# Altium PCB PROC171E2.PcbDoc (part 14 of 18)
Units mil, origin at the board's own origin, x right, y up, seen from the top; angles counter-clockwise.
Board outline 7700 x 2300 mil, 6 copper layers (Top Layer, GND 1, SIG 1, SIG 2, GND 2, Bottom Layer), stack 61.062 mil thick; 937 components, 687 nets, 11931 pads, 1719 vias.
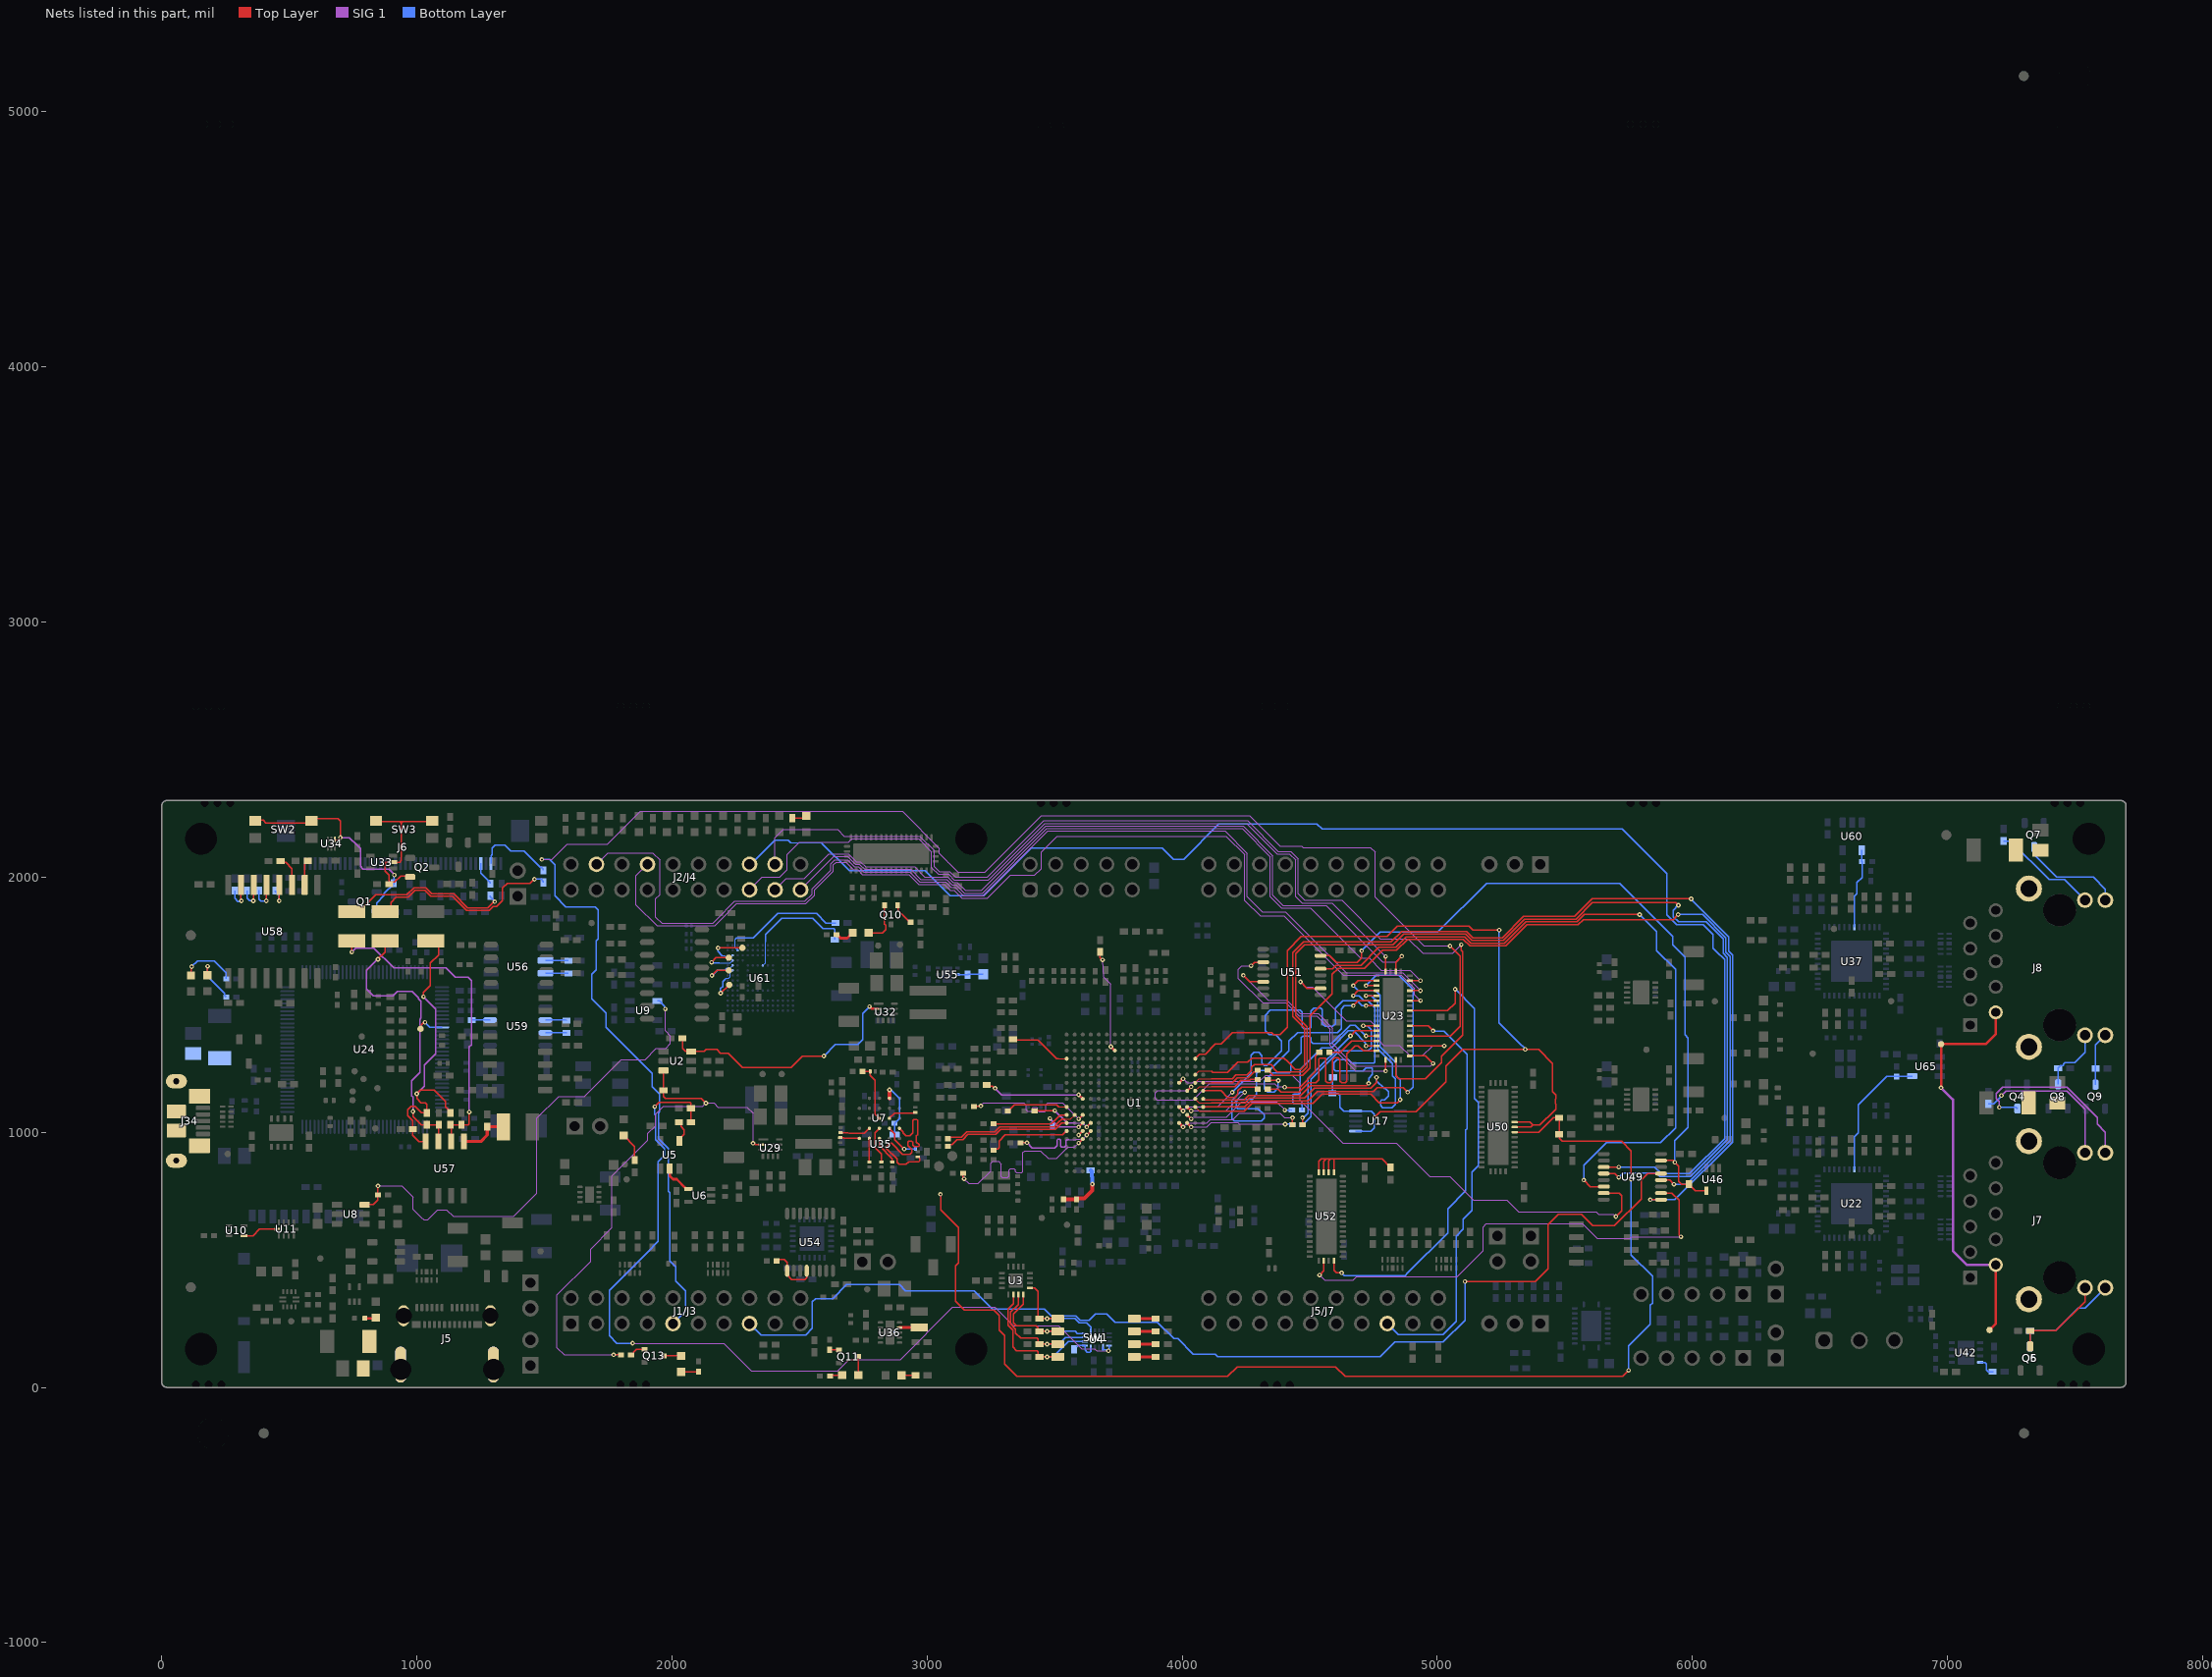
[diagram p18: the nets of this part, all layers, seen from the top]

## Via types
v1: diameter 18, hole 8, Top Layer to Bottom Layer, tented both sides, 1588 vias
v2: diameter 19.68, hole 7.87, Top Layer to Bottom Layer, tented both sides, 104 vias
v3: diameter 19.68, hole 7.87, Top Layer to Bottom Layer, 24 vias
v4: diameter 18, hole 8, Top Layer to Bottom Layer, 3 vias

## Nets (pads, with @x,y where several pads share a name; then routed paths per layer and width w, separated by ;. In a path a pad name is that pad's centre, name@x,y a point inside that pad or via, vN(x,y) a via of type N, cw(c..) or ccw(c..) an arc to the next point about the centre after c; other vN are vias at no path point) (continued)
NetC257_1: C257.1 R189.1 R190.1 U1.N3 | length 233.8
  Top Layer w5.3: v1(3594.38,989.09) U1.N3@3610.13,1004.84
  Top Layer w15: R190.1@3535,736.82 R189.1@3586.2,736.82 3586.2,738.78 3588.54,741.13 3617.5,741.13 3648.19,771.82 v1(3648.19,796.75)
  Bottom Layer w15: C257.1@3640.73,851 3641.45,851 3645.76,846.69 3645.76,826.66 3648.19,824.23 3648.19,815.87 v1(3648.19,796.75)
NetC266_1: C266.1 U61.C2 | length 497.7
  Bottom Layer w3.4: 2249.26,1757.01 2247.89,1755.65 2247.89,1722.93 U61.C2@2257.75,1713.07
  Bottom Layer w5.3: 2249.14,1757.13 2253.98,1761.97 2319.33,1761.97 2414.7,1857.34 2567.23,1857.34 2604.32,1820.24 C266.1@2641.33,1820.24
NetD2_2: D2.2 R257.1 | length 114.5
  Top Layer w5.3: D2.2@1810.94,987.31 1853.71,944.54 R257.1@1853.71,890.52
NetD3_2: D3.2 R259.1 | length 186.5
  Top Layer w5.3: D3.2@178.78,1615.52 179.85,1616.59 v1(179.85,1650.66)
  Bottom Layer w5.3: v1(179.85,1650.66) 179.85,1612.12 247.28,1544.69 247.28,1535.63 R259.1@252.92,1530
NetD4_2: D4.2 R313.1 | length 58.7
  Top Layer w5.3: R313.1@2471.37,2231 2517.62,2231 D4.2@2526.43,2239.8
NetD5_1: D5.1 Q13.3 | length 68.9
  Top Layer w5.3: Q13.3@1967.4,123.39 D5.1@2036.27,123.39
NetD5_2: D5.2 R314.1 | length 68
  Top Layer w5.3: D5.2@2036.27,60.4 2101.71,60.4 R314.1@2103.52,62.21
NetD6_2: D6.2 R315.1 | length 55
  Top Layer w5.3: D6.2@2899.99,47.06 2900.24,47.31 R315.1@2954.87,47.31
NetDS1_1: DS1.1 Q10.2 | length 169.1
  Top Layer w5.3: DS1.1@2770.91,1781.37 2824.91,1781.37 2837.72,1794.18 2837.72,1810.86 2833.47,1815.12 Q10.2@2833.47,1889.43
NetDS1_2: DS1.2 R265.1 | length 76.4
  Top Layer w12: R265.1@2645.6,1774.32 2647.57,1774.32 2661.07,1760.82 2687.37,1760.82 DS1.2@2707.92,1781.37
NetDS2_1: DS2.1 Q11.3 | length 73.1
  Top Layer w5.3: Q11.3@2729.93,120.9 2729.93,48.41 DS2.1@2730.37,47.97
NetDS2_2: DS2.2 R302.1 | length 49.3
  Top Layer w5.3: R302.1@2619.3,45 2622.27,47.97 DS2.2@2667.38,47.97
NetDS3_2: DS3.2 R260.1 | length 224.4
  Top Layer w5.3: DS3.2@115.08,1614.97 115.08,1646.45 v1@118.65,1650.03
  Bottom Layer w5.3: v1(117.38,1649.19) 139.6,1671.41 206.46,1671.41 252.92,1624.95 R260.1@252.92,1601.11
NetDS4_2: DS4.2 R434.1 | length 43.2
  Top Layer w10: R434.1@796.23,270.76 836.78,270.76 DS4.2@838.68,272.66
NetJ6_36: J6.36 R355.2 | length 94.1
  Bottom Layer w5.3: J6.36@1250.75,2053.35 1250.75,2015.97 1288.1,1978.61 R355.2@1288.1,1974.68
NetJ6_38: J6.38 R357.2 | length 311.3
  Bottom Layer w5.3: J6.38@1290.12,2053.35 1291.04,2054.27 1291.04,2083.42 1295.52,2087.91 1295.52,2114.52 1306,2125 1344.61,2125 1368.1,2101.52 1421.11,2101.52 1482.9,2039.72 1486.84,2039.72 1496,2030.56 R357.2@1496,2026.62
NetL4_1: L4.1 U36.9 | length 58.3
  Top Layer w10: U36.9@2892.11,234.65 2943.72,234.65 L4.1@2948.45,239.38
NetQ10_1: Q10.1 R272.2 | length 88.2
  Top Layer w5.3: Q10.1@2884.65,1889.43 2887.02,1887.06 2887.02,1869.67 2933.35,1823.35 R272.2@2935.31,1823.35
NetQ11_1: Q11.1 R303.2 | length 37.9
  Top Layer w5.3: R303.2@2617.63,147.36 2618.5,146.49 Q11.1@2655.13,146.49
NetQ13_1: Q13.1 R317.2 | length 63
  Top Layer w5.3: R317.2@1839.67,127.49 1841.64,127.49 1848.84,134.68 1848.84,136.65 1861.17,148.98 Q13.1@1892.6,148.98
NetR8_2: R8.2 U4.4 U4.5 | length 96.2
  Bottom Layer w5.3: R8.2@3586.45,158.78 3591.82,164.16 U4.5@3618.83,164.16 3618.83,146.31 3627.93,137.2 3637.86,137.2 3642.45,141.79 U4.4@3642.45,156.28
NetR22_2: R22.2 SW1.1 | length 84.4
  Top Layer w12: SW1.1@3812.01,119.51 R22.2@3896.38,119.51
NetR23_2: R23.2 SW1.2 | length 84.4
  Top Layer w12: SW1.2@3812.01,169.51 R23.2@3896.38,169.51
NetR24_2: R24.2 SW1.3 | length 84.4
  Top Layer w12: SW1.3@3812.01,219.51 R24.2@3896.38,219.51
NetR25_2: R25.2 SW1.4 | length 84.4
  Top Layer w12: SW1.4@3812.01,269.51 R25.2@3896.38,269.51
NetR165_2: R165.2 U1.M3 | length 178.3
  Top Layer w5.3: v1(3594.38,1020.59) U1.M3@3610.13,1036.34
  SIG 1 w5.3: v1(3481.61,1054.11) 3515.13,1020.59 v1(3594.38,1020.59)
  Bottom Layer w5.3: v1(3481.61,1054.11) 3481.61,1053.87 3490.83,1044.65 3490.83,1030.45 R165.2@3492.19,1029.09
NetR167_2: R167.2 U1.L1 | length 302.3
  Top Layer w5.3: R167.2@3260.59,1034.08 3262.76,1031.91 3487.02,1031.91 3515.64,1060.52 3522.95,1067.84 U1.L1@3547.13,1067.84
NetR168_2: R168.2 U1.K1 | length 242.4
  Top Layer w4: 3515.64,1099.42 3547.05,1099.42 U1.K1@3547.13,1099.33
  Top Layer w5.3: R168.2@3317.18,1083.59 3319.15,1083.59 3342.09,1106.53 3508.44,1106.53 3515.55,1099.42 3515.64,1099.42
NetR249_2: R249.2 U42.4 | length 81.8
  Bottom Layer w5.3: U42.4@7127.91,98.07 7147.67,98.07 7153.38,92.36 7153.38,68.08 7160,61.46 R249.2@7180.31,61.46
NetR256_2: R256.2 U52.18 U52.19 U52.20 U52.21 | length 504.7
  Top Layer w5.3: U52.21@4535.47,843.23 4535.47,885.47 4545.28,895.28 4565,895.28 ; U52.20@4555.16,843.23 4555.16,885.44 4565,895.28 ; U52.19@4574.84,843.23 4574.84,888.3 4581.82,895.28 ; U52.18@4594.53,843.23 4594.53,895.28 ; R256.2@4816.77,861.65 4783.14,895.28 4594.53,895.28 ; 4565,895.28 4581.82,895.28 ; 4581.82,895.28 4594.53,895.28
NetR342_1: R342.1 U58.15 | length 121
  Top Layer w5.3: U58.15@310.25,1969.74 310.2,1969.79 310.2,1908.8 v1(312,1907)
  Bottom Layer w5.3: R342.1@287,1947.38 287,1917 299,1905 v1@309,1905
NetR343_1: R343.1 U58.14 | length 119.6
  Top Layer w5.3: v1@358,1910 360.25,1912.25 U58.14@360.25,1969.74
  Bottom Layer w5.3: R343.1@334.13,1947.37 334.13,1917.87 345,1907 v1(359,1907)
NetR344_1: R344.1 U58.13 | length 125.7
  Top Layer w5.3: v1(410,1907) 410.25,1907.25 U58.13@410.25,1969.74
  Bottom Layer w5.3: R344.1@381.31,1947.65 381.31,1913.69 389,1906 v1@407,1906
NetR345_1: R345.1 U58.12 | length 111
  Top Layer w5.3: U58.12@460.25,1969.74 v1(460.25,1906.75) v1@461,1906
  Bottom Layer w5.3: R345.1@445,1947.38 445,1943.71 460.25,1928.46 v1(460.25,1906.75)
NetR349_1: R349.1 U58.11 | length 114.3
  Top Layer w5.3: R349.1@471,2061.94 475.53,2057.41 486.59,2057.41 510.51,2033.49 U58.11@510.51,1970.49
NetR353_1: R353.1 U58.10 | length 104
  Top Layer w5.3: U58.10@560.25,1969.74 560.25,2054.84 570.41,2065 R353.1@575,2065
NetR359_1: R359.1 U59.7 | length 82.8
  Bottom Layer w5.3: U59.7@1503.89,1390 R359.1@1586.63,1390
NetR362_1: R362.1 R363.2 U55.2 | length 102.1
  Bottom Layer w5.3: U55.2@3118.68,1617.97 3158.86,1617.97 R363.2@3159.18,1617.65 3160.81,1619.28 R362.1@3220.04,1619.32
NetR377_2: R377.2 U1.N1 | length 332.9
  Top Layer w5.3: R377.2@3260.59,929.6 3265.73,934.74 3277.24,934.74 3282.45,939.94 3282.45,965.9 3306.05,989.51 3515.64,989.51 3531.8,989.51 U1.N1@3547.13,1004.84
NetR378_2: R378.2 U1.N4 | length 377.5
  Top Layer w5.3: R378.2@3366.16,958.84 v1(3391.73,958.83) ; v1(3625.87,989.09) 3627.77,989.09 3641.62,1002.95 U1.N4@3641.62,1004.84
  SIG 1 w4: 3556.48,970.8 3582.97,970.8 3584.78,972.6 3611.27,972.6 3625.87,987.2 v1(3625.87,989.09)
  SIG 1 w5.3: v1(3391.73,958.83) 3411.89,938.67 3500,938.67 3509.35,948.02 3509.35,969.76 3512.46,972.86 3520.44,972.86 3523.55,969.76 3523.55,944.95 3526.65,941.85 3538.96,941.85 3544.9,947.8 3544.9,966.72 3548.98,970.8 3556.48,970.8
NetR379_2: R379.2 U1.M4 | length 259.6
  Top Layer w5.3: R379.2@3415.53,1083.59 R379.2@3421.62,1083.62 3497.17,1083.62 v1@3498.06,1084.5 ; v1@3498.06,1084.68 v1(3500.62,1084.68) ; v1(3625.87,1020.59) U1.M4@3641.62,1036.34
  SIG 1 w4: 3578.64,1035.53 3578.7,1035.59 3610.87,1035.59 v1(3625.87,1020.59)
  SIG 1 w5.3: v1(3500.62,1084.68) 3549.77,1035.53 3578.64,1035.53
NetR380_2: R380.2 U1.P3 | length 763.5
  Top Layer w5.3: R380.2@3140.83,838.71 3140.83,825.06 3145.01,820.88 v1(3145.01,817.45) ; v1(3594.38,957.6) U1.P3@3610.13,973.35
  SIG 1 w4.75: v1(3145.01,817.45) 3163.35,799.11 3200.23,799.11 3249.46,848.34 3249.46,877.71 3257.49,885.74 3280.43,885.74 3291.38,874.79 3291.38,826.69 3294.84,823.24 3316.37,823.24 3321.97,828.84 3321.97,851.68 3327.83,857.55 3341.45,857.55 3346.92,852.08 3346.92,845.62 3350.58,841.96 3371.25,841.96 3375.91,846.62 3375.91,920.86 3382.23,927.18 3444.51,927.18 3474.6,897.1 3507.88,897.1 3552.26,941.48 3578.26,941.48 v1(3594.38,957.6)
NetR381_2: R381.2 R382.2 U7.C3 | length 229.2
  Top Layer w5.3: R382.2@2747.63,1238.43 R381.2@2777.12,1238.43 2777.12,1222.96 2796.54,1203.54 2796.54,1071.29 2811.83,1056.01 2813.29,1056.01 U7.C3@2813.29,1054.55
NetR393_2: R393.2 U1.J3 | length 404.2
  Top Layer w5.3: R393.2@3229.9,1188.7 3232.26,1188.7 3239.97,1180.98 3256.83,1180.98 3265.45,1172.36 v1(3266.28,1172.36)
  Top Layer w10: v1(3594.38,1146.58) U1.J3@3610.13,1130.83
  SIG 1 w5: v1(3266.28,1172.36) 3292.07,1146.58 v1(3594.38,1146.58)
NetR394_2: R394.2 U54.9 U54.12 | length 208.6
  Top Layer w5.3: R394.2@2410.52,501.44 2440.5,501.44 2451.64,490.31 U54.9@2451.64,457 2451.64,441.25 2469.56,423.33 2521.51,423.33 2528.41,430.22 U54.12@2528.41,457
NetR401_2: R401.2 U1.C7 | length 409.9
  Top Layer w5.3: R401.2@3678.01,1706.38 3678.01,1685.26 v1(3687.73,1675.54)
  Top Layer w10: v1(3720.36,1335.55) U1.C7@3736.11,1319.8
  SIG 1 w4.75: v1(3687.73,1675.54) 3686.15,1673.97 3686.15,1673.24 3691.8,1609.1 3693.19,1607.71 3720.36,1580.54 v1(3720.36,1335.55)
NetR402_2: R402.2 U1.L3 | length 538.7
  Top Layer w5.3: R402.2@3184.32,1100.9 3185.45,1102.03 3209.41,1102.03 v1(3210.7,1103.32) ; v1(3594.38,1052.09) U1.L3@3610.13,1067.84
  SIG 1 w4.75: v1(3210.7,1103.32) 3210.7,1103.67 3221.83,1114.8 3379.81,1114.8 3388.16,1106.45 3388.16,1087.69 3392.82,1083.03 3410.27,1083.03 3413.55,1086.32 3413.55,1094.87 3416.33,1097.66 3429.74,1097.66 3432.52,1094.87 3432.52,1087.1 3439.23,1080.39 3461.7,1080.39 3465.04,1083.72 3465.04,1106.36 3473.48,1114.8 3531.66,1114.8 3556.79,1089.67 v1(3594.38,1052.09)
NetR403_2: R403.2 U1.M1 | length 502.7
  Top Layer w5.3: R403.2@3082.47,944.62 3088.71,950.87 3098.52,950.87 3118.11,970.45 3139.8,970.45 3160.61,991.26 3269.76,991.26 3289.21,1010.7 3502.16,1010.7 3515.64,1024.19 3527.79,1036.34 U1.M1@3547.13,1036.34
NetR404_2: R404.2 U1.L2 | length 534.7
  Top Layer w4: 3537.53,1052.09 3562.88,1052.09 U1.L2@3578.63,1067.84
  Top Layer w5.3: R404.2@3082.47,974.88 3088.64,981.05 3135.41,981.05 3156.64,1002.28 3265.79,1002.28 3284.82,1021.3 3497.77,1021.3 3515.64,1039.18 3528.55,1052.09 3537.53,1052.09
NetR405_1: R405.1 R406.1 R407.2 R408.2 U57.8 | length 1241.2
  Top Layer w5.3: v1(1026.05,1531.2) 1026.05,1547.56 1052.73,1574.24 1052.73,1662.86 1085.04,1695.17 1085.04,1727.55 1062.1,1750.49 R406.1@1054.16,1750.49 ; U57.8@1034.51,963.77 1008.25,963.77 984.16,987.86 R405.1@984.16,1011.75 984.16,1045.27 964.95,1064.48 964.95,1088.93 976.75,1100.72 992.92,1100.72 1017.44,1076.19 R408.2@1039.15,1076.19 1039.15,1108.53 1032.63,1115.05 1016.49,1115.05 999.85,1131.69 v1(999.85,1150.84) 1014.08,1165.07 1068.66,1165.07 1112.67,1121.06 1112.67,1098.79 1131.33,1080.13 R407.2@1131.33,1076.19
  SIG 1 w5.3: v1(999.85,1150.84) 1029.7,1180.69 1029.7,1230.56 1029.7,1263.41 1074.7,1308.4 1074.7,1482.55 v1(1026.05,1531.2)
NetR407_1: R407.1 R412.1 R414.1 U57.6 | length 1279.9
  Top Layer w5.3: v1(745.15,1706.15) 745.15,1750.25 R412.1@745.39,1750.49 ; U57.6@1134.51,963.77 1134.51,1025.77 R407.1@1131.33,1028.95 R414.1@1174.89,1028.95 1201.32,1028.95 1205.5,1033.13 v1(1205.5,1078.98)
  SIG 1 w5.3: v1(745.15,1706.15) 760.84,1721.84 831.48,1721.84 909.35,1643.97 1114.77,1643.97 1150.04,1608.7 1200.21,1608.7 1213.8,1595.11 1213.8,1342.91 1205.5,1334.61 v1(1205.5,1078.98)
NetR408_1: R408.1 R410.1 R413.1 U57.7 | length 1114.2
  Top Layer w5.3: v1(847.55,1678.16) 875.14,1705.75 R410.1@875.14,1750.49 ; v1(984.83,1081.19) 984.83,1061.83 1017.71,1028.95 R408.1@1039.15,1028.95 R413.1@1085.82,1028.95 1084.51,1027.65 U57.7@1084.51,963.77
  SIG 1 w5.3: v1(847.55,1678.16) 803.37,1633.98 803.37,1562.05 830.36,1535.07 906.82,1535.07 923.1,1551.34 981.25,1551.34 1006.53,1526.06 1006.53,1523.12 1015.26,1514.38 1015.26,1447.14 1011.34,1443.21 1011.34,1233.52 980.32,1202.51 980.32,1142.95 984.48,1138.8 984.48,1081.55 v1(984.83,1081.19)
NetR409_1: R409.1 U56.7 | length 90
  Bottom Layer w5.3: U56.7@1504.02,1623.36 1593.16,1623.36 R409.1@1593.78,1622.73
NetR411_1: R411.1 U56.6 | length 90.4
  Bottom Layer w5.3: U56.6@1504.02,1673.36 1593.73,1673.36 R411.1@1594.25,1672.84
NetR415_1: R415.1 R416.1 U57.5 | length 199.1
  Top Layer w12: U57.5@1184.51,963.77 1250.92,963.77 1275.96,988.81 R416.1@1275.96,1022.41 1337.63,1022.41 R415.1@1339.03,1021.01
NetR419_1: R419.1 U61.H5 | length 481.4
  Bottom Layer w3.4: U61.H5@2356.18,1654.01 2366.01,1663.84 2366.01,1746.56
  Bottom Layer w5.3: 2366.01,1746.56 2366.01,1774.99 2429.91,1838.89 2551.31,1838.89 2557.05,1833.15 2591.82,1798.38 2604.21,1798.38 2633.89,1798.38 2638.32,1793.95 R419.1@2638.32,1755.01
NetR427_1: R427.1 U59.3 | length 71.4
  Bottom Layer w5.3: R427.1@1215.7,1439.56 1216.14,1440 U59.3@1286.89,1440
NetR428_2: R428.2 U59.6 | length 83.7
  Bottom Layer w5.3: U59.6@1503.89,1440 1584.33,1440 R428.2@1586.66,1437.67
NetR433_2: R433.2 U1.D1 | length 242.2
  Top Layer w4: 3515.64,1288.31 U1.D1@3547.13,1288.31
  Top Layer w5.3: R433.2@3336.43,1364.34 3339.71,1361.06 3435.14,1361.06 3507.89,1288.31 3515.64,1288.31
NetTP31_1: TP31.1 U24.75 | length 109.6
  Top Layer w5.3: TP31.1@1014.53,1405.29 1018.3,1409.06 1018.3,1420.62 1028.41,1430.74 v1(1031.79,1430.74)
  Bottom Layer w5.3: v1(1031.79,1430.74) 1051.54,1410.98 U24.75@1098.65,1410.98
NetTP35_1: TP35.1 U61.B3 | length 181.3
  Top Layer w5.3: v1(2180.49,1722.55) 2228.58,1722.55 2228.84,1722.81 TP35.1@2276.01,1722.81
  Bottom Layer w3.4: 2196.29,1693.38 2204.63,1693.38 2208.56,1689.45 2208.56,1689.31 2214.31,1683.56 2228.24,1683.56 U61.B3@2238.07,1693.38
  Bottom Layer w5.3: v1(2180.49,1722.55) 2180.49,1709.18 2196.29,1693.38
NetTP36_1: TP36.1 U61.B4 | length 162.9
  Top Layer w5.3: v1(2155.31,1665.99) 2173.16,1683.84 TP36.1@2223.1,1683.84
  Bottom Layer w3.4: 2186.57,1664.16 2214.03,1664.16 2214.31,1663.87 2228.24,1663.87 U61.B4@2238.07,1673.7
  Bottom Layer w5.3: v1(2155.31,1665.99) 2157.15,1664.16 2186.57,1664.16
NetTP37_1: TP37.1 U61.B5 | length 172
  Top Layer w5.3: v1(2156.86,1614.52) 2176.6,1634.27 TP37.1@2223.1,1634.27
  Bottom Layer w3.4: 2204.33,1634.27 2214.25,1644.19 2228.24,1644.19 U61.B5@2238.07,1654.01
  Bottom Layer w5.3: v1(2156.86,1614.52) 2159.5,1614.52 2179.25,1634.27 2204.33,1634.27
NetTP38_1: TP38.1 U61.B6 | length 161.4
  Top Layer w5.3: v1(2190.84,1545.39) 2191.4,1545.39 2223.62,1577.6 TP38.1@2224.18,1577.6
  Bottom Layer w3.4: 2209.63,1600.53 2213.89,1604.78 2222.41,1604.78 2228.11,1610.48 2228.2,1610.57 2228.2,1618.71 2228.11,1618.8 2228.11,1624.38 U61.B6@2238.07,1634.33
  Bottom Layer w4: 2209.17,1600.99 2210.09,1600.99
  Bottom Layer w5.3: v1(2190.84,1545.39) 2190.84,1562.59 2198.63,1570.39 2198.63,1590.45 2209.17,1600.99
NetU10_4: U10.4 U11.5 | length 141.4
  Top Layer w5.3: U10.4@321.92,594.53 357.03,594.53 382.5,620 U11.5@452.76,620
OSPI0_D0: R27.2 U7.D3 | length 148.7
  Top Layer w5.3: U7.D3@2813.29,1015.18 2796.54,998.44 2796.54,939.84 2820.72,915.66 R27.2@2820.72,883.42
OSPI0_D1: R28.2 U7.D2 | length 122.8
  Top Layer w5.3: R28.2@2660.72,998.28 2691.13,998.28 2694.28,995.13 2753.86,995.13 U7.D2@2773.92,1015.18
OSPI0_D2: R29.2 U7.C4 | length 111.2
  Top Layer w5.3: U7.C4@2852.66,1054.55 2873.06,1074.96 2951.36,1074.96 R29.2@2954.22,1077.82
OSPI0_D3: R30.2 U7.D4 | length 150.7
  Top Layer w5.3: U7.D4@2852.66,1015.18 2873.71,994.13 2873.71,970.45 2909.91,934.25 v1(2910.59,934.25)
  Bottom Layer w5.3: v1(2910.59,934.25) 2911.25,934.91 2954.78,934.91 R30.2@2955.43,935.56
OSPI0_D4: R361.2 U7.D5 | length 680.2
  Top Layer w5.3: U7.D5@2892.03,1015.18 2904.91,1002.3 2904.91,997.68 2916.34,986.24 2932.52,986.24 2934.07,987.79 2943.96,997.68 2943.96,1045.97 2948.01,1050.03 2959.45,1050.03 2962.56,1046.92 2962.56,990.45 2957.88,985.77 2957.88,961.49 2968.74,950.63 2968.74,946.24 2965.64,943.14 2950.86,943.14 2944.37,949.63 2944.37,960.84 2939.26,965.96 2929.13,965.96 2924.4,961.22 2924.4,948.05 2940.64,931.82 2940.64,921.69 2931.92,912.98 2904.26,912.98 2860.6,956.63 2856.21,956.63 2841.01,941.43 2841.01,937.04 2882.43,895.63 2882.43,881.58 2890.34,873.67 2917.66,873.67 2927.98,884 2967.12,884 2970.22,887.11 2970.22,897.71 2970.02,897.92 2970.02,900.82 2967.16,903.68 R361.2@2964.2,903.68
OSPI0_D5: R365.2 U7.E3 | length 113.4
  Top Layer w5.3: U7.E3@2813.29,975.81 2813.29,947.02 2863.91,896.4 R365.2@2863.91,883.42
OSPI0_D6: R366.2 U7.E2 | length 92.4
  Top Layer w5.3: R366.2@2773.92,883.42 U7.E2@2773.92,975.81
OSPI0_D7: R376.2 U7.E1 | length 74.3
  Top Layer w5.3: R376.2@2661.56,978.93 2661.83,978.66 2672.68,978.66 2674.79,976.54 2733.81,976.54 U7.E1@2734.55,975.81
OSPI0_RST: R388.1 U7.A4 U35.4 | length 235.9
  Top Layer w15: U7.A4@2852.66,1133.29 v1(2852.66,1165.79)
  Bottom Layer w5.3: v1(2852.66,1165.79) 2855.09,1163.36 2861.82,1163.36 2878.44,1146.74 2892.11,1133.07 2892.11,1054.27 R388.1@2872.58,1034.74 R388.1@2872.58,1034.74 U35.4@2872.65,990.75
PG_VDD_1V2: R295.1 R317.1 U2.3 U29.5 | length 2188
  Top Layer w5.3: v1(1771.58,127.81) 1771.9,127.49 R317.1@1800.3,127.49 ; U2.3@1967.11,1242.05 1967.11,1164.31 R295.1@1966.38,1163.59 1966.38,1140.77 1975.03,1132.12 2115.19,1132.12 v1(2133.03,1114.29) ; v1(2318.17,956.75) 2321.61,956.75 2326.83,951.52 U29.5@2351.44,951.52
  SIG 1 w4.75: v1(1771.58,127.81) 1577.19,127.81 1549.15,155.85 1549.15,361.93 1680.95,493.74 1680.95,496.44 1681.22,496.72 1681.22,541.23 1765.47,625.48 1765.47,829.29 1905.93,969.75 1905.93,995.2 1936.08,1025.35 1936.08,1071.8 1966.79,1102.51 2121.25,1102.51 v1(2133.03,1114.29) 2164.62,1114.29 2180.23,1098.68 2294.53,1098.68 2318.17,1075.03 v1(2318.17,956.75)
PG_VSYS_3V3: R296.1 U2.6 U32.5 | length 999.9
  Top Layer w5.3: R296.1@2041.1,1367.85 2041.1,1329.7 2053.94,1316.85 U2.6@2075.37,1316.85 2126.3,1316.85 2133.9,1324.45 2175.67,1324.45 2190.08,1310.03 2220.88,1310.03 2276.42,1254.49 2466.27,1254.49 2510.68,1298.9 v1(2595.37,1298.9)
  Top Layer w10: v1(2774.69,1492.62) 2783.16,1484.14 U32.5@2803.11,1484.14
  Bottom Layer w5.3: v1(2595.37,1298.9) 2640.19,1343.72 2728.42,1343.72 2747.31,1362.61 2747.31,1465.24 v1(2774.69,1492.62)
PHY1_RST: R425.1 U22.43 U65.4 | length 517.5
  Bottom Layer w5.3: U22.43@6635.02,853.9 6635.02,982.42 6650.65,998.04 6650.65,1107.31 6761.52,1218.19 R425.1@6800.32,1218.19 6801.98,1219.85 U65.4@6861.67,1219.85
PHY2_RST: R418.1 U37.43 U60.4 | length 314.9
  Bottom Layer w5.3: U37.43@6635.02,1803.9 6635.02,1924.8 6644.66,1934.45 6644.66,1978.73 6665.24,1999.31 R418.1@6665.24,2060.88 6663.66,2062.46 U60.4@6663.66,2105.64
PORZ_DELAY: U5.2 U6.4 | length 123.2
  Top Layer w10: U5.2@1991.31,857.27 1991.31,828.7 2004.18,815.84 2018.65,815.84 2052.65,781.84 2052.65,780.85 2055.52,777.98 U6.4@2064.38,777.98
PORZ_PB: Q1.2 R177.1 SW2.2 SW2.4 U34.1 | length 923.3
  Top Layer w4: U34.1@678.78,2146.97 691.97,2146.97 v1(700,2155)
  Top Layer w5.3: SW2.2@366.76,2220.46 369.3,2223 398,2223 408.43,2212.57 579.35,2212.57 595.77,2229 691,2229 700,2220 v1(700,2155)
  SIG 1 w5.3: v1(700,2155) 736.01,2155 765,2126 765,2124.81 778.65,2111.16 778.65,2041.94 789.59,2031 891,2031 v1@913,2009
  Bottom Layer w5.3: Q1.2@842.87,1866.72 842.87,1899.27 872.61,1929.01 872.61,1936.17 909.28,1972.85 909.28,2001.85 912,2004.56 v1(912,2008)
PR0_PRU0_GPIO0: U1.K17 U23.2 | length 1519.8
  Top Layer w4: U1.K17@4051.07,1099.33 4068.69,1081.71 4114.06,1081.71
  Top Layer w5.3: 4114.06,1081.71 4242.57,1081.71 4272.05,1111.19 4273.6,1112.74 4351.32,1112.74 4363.32,1113.1 4363.52,1113.1 ccw(c4363.33,1118.4) 4363.71,1113.11 4512.29,1113.11 4548.71,1149.54 4738.98,1149.54 4772.52,1116 4843.09,1116 v1(4854.47,1127.38) ; v1(4670.59,1574.61) 4690.28,1594.29 U23.2@4762.24,1594.29
  Bottom Layer w5.3: v1(4670.59,1574.61) 4690.11,1555.09 4757.29,1555.09 4776.23,1536.14 4776.23,1334.57 4837.59,1273.22 4837.59,1221.87 4854.47,1204.98 v1(4854.47,1127.38)
PR0_PRU0_GPIO0_MUX: J2/J4.33 U23.42 | length 3166.9
  Top Layer w5.3: U23.42@4797.68,1629.73 v1(4797.68,1689)
  SIG 1 w4.75: J2/J4.33@2304.17,1950 2354.15,1999.98 2423.45,1999.98 2451.78,2028.31 2451.78,2089.76 2499.16,2137.13 2691.64,2137.13 2705.33,2150.82 2966.6,2150.82 3018.07,2099.36 3018.07,2036.64 3043.45,2011.27 3084.82,2011.27 3106.66,1989.43 3240.53,1989.43 3461.82,2210.72 4251.82,2210.72 4371.78,2090.76 4421.06,2090.76 4444.93,2066.88 4444.93,1924.26 4470,1899.19 4587.49,1899.19 v1(4797.68,1689)
PR0_PRU0_GPIO1: U1.K18 U23.3 | length 1516.1
  Top Layer w5.3: U1.K18@4082.57,1099.33 4245.2,1099.33 4269.58,1123.71 4492.67,1123.71 4529.1,1160.14 4748.73,1160.14 4764.08,1175.48 4865.69,1175.48 v1(4883.93,1157.24) ; v1(4720.59,1574.61) U23.3@4762.24,1574.61
  Bottom Layer w5.3: v1(4720.59,1574.61) 4761.04,1615.05 4848.61,1615.05 4904.17,1559.5 4904.17,1177.49 v1(4883.93,1157.24)
PR0_PRU0_GPIO1_MUX: J2/J4.32 U23.40 | length 3070.7
  Top Layer w5.3: U23.40@4837.05,1629.73 4837.05,1666.14 v1(4860.91,1690)
  SIG 1 w4.75: J2/J4.32@2404.17,1950 2448.22,1994.04 2519.19,1995.39 2615.04,2091.24 2692.98,2091.24 2723.7,2060.52 2739.25,2060.52 2759.34,2040.43 2952.07,2040.43 2991.28,2001.22 3080.66,2001.22 3102.5,1979.38 3118.1,1979.38 3149.83,1947.64 3212.96,1947.64 3465.99,2200.67 4238.82,2200.67 4355.61,2083.87 4355.61,1928.53 4395,1889.14 4563.86,1889.14 4786,1667 4837.91,1667 v1(4860.91,1690)
PR0_PRU0_GPIO2: U1.J18 U23.4 | length 1516.8
  Top Layer w5.3: U1.J18@4082.57,1130.83 4086.86,1126.53 4242.42,1126.53 4260.8,1144.91 4464.36,1144.91 4502.13,1182.68 4722.08,1182.68 v1(4731.01,1191.61) ; v1(4670.59,1535.24) 4690.28,1554.92 U23.4@4762.24,1554.92
  Bottom Layer w5.3: v1(4670.59,1535.24) 4692.98,1535.24 4712.83,1515.39 4728.68,1515.39 4755,1489.07 4755,1275.07 4751.15,1271.22 4663.78,1271.22 4650.2,1284.8 4606.38,1284.8 4595,1273.42 4595,1246.63 4600.67,1240.95 4708.91,1240.95 4720.52,1252.57 4742.9,1252.57 4746,1249.47 4746,1226.84 4731.01,1211.85 v1(4731.01,1191.61)
PR0_PRU0_GPIO2_MUX: J2/J4.31 U23.37 | length 3028.4
  Top Layer w5.3: U23.37@4892.17,1594.29 v1(4933.82,1594.29)
  SIG 1 w4.75: J2/J4.31@2504.17,1950 2635.37,2081.19 2688.82,2081.19 2719.6,2050.41 2735.15,2050.41 2755.18,2030.38 2936.23,2030.38 2975.45,1991.17 3076.5,1991.17 3098.34,1969.32 3113.93,1969.32 3145.67,1937.59 3217.12,1937.59 3470.15,2190.62 4234.65,2190.62 4345.27,2080 4345.27,1923.82 4390,1879.09 4502.91,1879.09 4699.99,1682.01 4733.4,1682.01 4780.53,1634.88 4893.23,1634.88 v1(4933.82,1594.29)
PR0_PRU0_GPIO3: U1.J17 U23.5 | length 1518.5
  Top Layer w4: U1.J17@4051.07,1130.83 4065.96,1115.93 4114.06,1115.93
  Top Layer w5.3: 4114.06,1115.93 4246.81,1115.93 4265.19,1134.31 4480.07,1134.31 4517.85,1172.08 4739.09,1172.08 4762.04,1195.03 v1(4762.04,1215.27) ; v1(4720.59,1535.24) U23.5@4762.24,1535.24
  Bottom Layer w5.3: v1(4720.59,1535.24) 4741.8,1535.24 4765.63,1511.4 4765.63,1327.07 4824.32,1268.39 4824.32,1220.15 4834.95,1209.51 4834.95,1109.8 4821.54,1096.38 4785.96,1096.38 4777.36,1104.98 4777.36,1123.49 4780.46,1126.6 4793.49,1126.6 4809.6,1142.71 4809.6,1159.77 4798.17,1171.21 4792.65,1171.21 4761.31,1202.54 4761.31,1214.54 v1(4762.04,1215.27)
PR0_PRU0_GPIO3_MUX: J2/J4.19 U23.35 | length 4207.2
  Top Layer w5.3: U23.35@4892.17,1554.92 v1(4933.82,1554.92)
  SIG 1 w4.75: J2/J4.19@1704.17,2050 1749.17,2095 1925,2095 1952.52,2067.48 1952.52,1931.18 1936.83,1915.5 1936.83,1843.2 1960.52,1819.52 2088.46,1819.52 2160.17,1819.52 2173.8,1833.15 2246.34,1905.69 2521.4,1905.69 2549.29,1933.57 2549.29,1953.8 2622.35,2026.86 2622.35,2050.45 ccw(c2618.89,2053.71) 2623.27,2051.86 ; 2623.28,2051.88 2639.18,2067.78 2688.02,2067.78 2696.67,2059.12 2715.43,2040.36 2730.99,2040.36 2751.02,2020.33 2932.07,2020.33 2971.28,1981.12 3072.33,1981.12 3094.17,1959.28 3109.77,1959.28 3141.51,1927.54 3221.28,1927.54 3474.31,2180.57 4167.16,2180.57 4255,2092.73 4255,1924.04 4315.04,1864 4404.5,1864 4643.67,1624.83 4863.91,1624.83 v1(4933.82,1554.92)
PR0_PRU0_GPIO4: U1.K16 U23.6 | length 1518.6
  Top Layer w5.3: v1(4670.59,1495.87) 4690.28,1515.55 U23.6@4762.24,1515.55
  Top Layer w10: U1.K16@4019.57,1099.33 v1(4035.32,1083.58)
  SIG 1 w4.75: v1(4035.32,1083.58) 4171.86,1083.58 v1(4244.93,1156.66)
  Bottom Layer w5.3: v1(4244.93,1156.66) 4226.95,1156.66 4195.86,1125.57 4195.86,1052.83 4204.94,1043.75 4310.25,1043.75 4321.85,1055.35 4321.85,1068.6 4297.69,1092.76 4219.07,1092.76 4211.79,1100.03 4211.79,1121.09 4220.2,1129.5 4273.31,1129.5 4291.03,1147.23 4291.03,1229.74 4303.98,1242.68 4341.65,1242.68 4418.23,1319.26 4418.23,1356.94 4452.05,1390.76 4609.04,1390.76 4623.28,1405 4623.28,1482.76 4636.39,1495.87 v1(4670.59,1495.87)
PR0_PRU0_GPIO4_MUX: J2/J4.17 U23.33 | length 4041.5
  Top Layer w5.3: U23.33@4892.17,1515.55 v1(4934.43,1515.55)
  SIG 1 w4.75: J2/J4.17@1904.17,2050 1859.69,2005.52 1859.69,1890.49 1940.72,1809.47 2088.46,1809.47 2168.12,1809.47 2191.8,1833.15 2254.29,1895.64 2525.57,1895.64 2559.34,1929.41 2559.34,1933.3 cw(c2564.09,1933.3) 2559.34,1933.5 2559.5,1937.3 2559.5,1949.8 2633.33,2023.63 2633.33,2047.72 2643.34,2057.73 2682.31,2057.73 2710.98,2029.06 2728.07,2029.06 2746.85,2010.28 2927.9,2010.28 2967.12,1971.07 3068.17,1971.07 3090.01,1949.22 3105.61,1949.22 3137.34,1917.49 3236.7,1917.49 3326.48,2007.27 3421.87,2007.27 3448.18,2033.57 3448.18,2099.21 3509.93,2160.97 4172.55,2160.97 4244.93,2088.58 4244.93,1908.32 4305.75,1847.5 4399,1847.5 4631.72,1614.78 4859.05,1614.78 4911.11,1562.72 4911.11,1538.87 v1(4934.43,1515.55)
PR0_PRU0_GPIO5: U1.G17 U49.4 | length 4214
  Top Layer w4: U1.G17@4051.07,1193.82 4066.82,1209.57 4114.06,1209.57
  Top Layer w5.3: 4114.06,1209.57 4196.83,1209.57 4211.2,1223.93 4255.03,1223.93 4272.68,1241.58 4272.68,1255.67 4282.71,1265.71 4349.14,1265.71 4358.99,1255.86 4358.99,1249.6 4372.91,1235.68 4469.28,1235.68 4490.12,1256.53 4490.12,1412.6 4444.48,1458.25 4444.48,1699.98 4479.9,1735.4 4826.4,1735.4 4867.89,1776.89 5111.1,1776.89 5136.35,1751.64 5259.36,1751.64 5342.82,1835.1 5543.35,1835.1 5608,1899.74 5935.26,1899.74 v1(5945,1890) ; U49.4@5652.8,838.02 5696.58,838.02 v1(5711.38,823.23)
  Bottom Layer w5.3: v1(5711.38,823.23) 5728.96,840.81 5860.01,840.81 5873.54,827.28 5993.25,827.28 6136.91,970.94 6136.91,1684.96 6120.62,1701.25 6120.62,1757.66 6053.94,1824.33 5945.45,1824.33 5924.62,1845.16 5924.62,1869.62 v1(5945,1890)
PR0_PRU0_GPIO5_MUX: J2/J4.13 U49.3 | length 5692
  Top Layer w5.3: U49.3@5652.8,863.61 v1(5711.38,863.61)
  Bottom Layer w5.3: J2/J4.13@2304.17,2050 2308.74,2050 2403.79,2145.05 2455,2145.05 2465.02,2135.03 2465.57,2134.48 2587.45,2133.48 2589.01,2131.93 2695.95,2024.98 2992.53,2024.98 3089.78,1927.73 3220.73,1927.73 3407.38,2114.38 3921.61,2114.38 3965.46,2070.53 4005.48,2070.53 4142.86,2207.91 4528.68,2207.91 4548.59,2188.01 5725.18,2188.01 5899.18,2014.02 5899.18,1852.75 5938.19,1813.73 6043.16,1813.73 6081.57,1775.32 6081.57,1721.18 6094.4,1708.34 6126.31,1676.43 6126.31,975.33 5988.86,837.88 5877.94,837.88 5852.2,863.61 v1(5711.38,863.61)
PR0_PRU0_GPIO6: U1.K15 U23.7 | length 1517.1
  Top Layer w5.3: v1(4720.59,1495.87) U23.7@4762.24,1495.87
  Top Layer w10: U1.K15@3988.08,1099.33 v1(4003.83,1083.58)
  SIG 1 w4.75: v1(4003.83,1083.58) 4020.24,1100 4140.09,1100 v1(4196.74,1156.66)
  Bottom Layer w5.3: v1(4196.74,1156.66) 4270.24,1230.15 4270.24,1302.02 4281.65,1313.43 4300,1313.43 4312.89,1300.54 4312.89,1270.44 4321.85,1261.48 4331.72,1261.48 4390,1319.76 4390,1358.24 4366.43,1381.81 4341.25,1381.81 4325,1398.06 4325,1458.62 4345.5,1479.12 4461.67,1479.12 4469.35,1471.45 4469.35,1413.42 4477.77,1405 4496.97,1405 4504.23,1412.26 4504.23,1474.23 4516.68,1486.68 4543.64,1486.68 4550,1480.32 4550,1425.91 4560.91,1415 4590,1415 4600.62,1425.62 4600.62,1486.68 4629.34,1515.39 4685.27,1515.39 4704.79,1495.87 v1(4720.59,1495.87)
PR0_PRU0_GPIO6_MUX: J5/J7.48 U23.31 | length 1930.5
  Top Layer w5.3: U23.31@4892.17,1476.18 5040,1476.18 5070,1506.18 v1(5070,1560.88)
  Bottom Layer w5.3: J5/J7.48@4804.17,250 4847.17,207 5022,207 5073.93,258.93 5073.93,592.64 5101.26,619.97 5101.26,658.67 5135.6,693.01 5135.6,843.47 5161.9,869.76 5161.9,1116.79 5146.42,1132.27 5146.42,1484.46 v1(5070,1560.88)
PR0_PRU0_GPIO8: U1.G15 U49.7 | length 2171
  Top Layer w5.3: U49.7@5652.8,761.25 5713.35,761.25 5722.21,752.39 5722.21,691.43 v1(5700.39,669.61)
  Top Layer w10: U1.G15@3988.08,1193.82 v1(4003.83,1209.57)
  SIG 1 w4.75: v1(4003.83,1209.57) 4019.2,1194.19 4041.69,1194.19 4047.02,1199.52 4302.96,1199.52 4327.29,1223.85 4431.06,1223.85 4462.51,1192.39 4462.51,1125.71 4630.59,957.64 4839.34,957.64 4971.11,825.87 5050.22,825.87 5142.33,733.76 5272.62,733.76 5318.3,688.07 5622.92,688.07 5633.16,677.83 5690.98,677.83 5699.2,669.61 v1(5700.39,669.61)
PR0_PRU0_GPIO8_MUX: U49.6 U51.13 | length 2820.6
  Top Layer w5.3: U51.13@4542.2,1640.71 4590,1640.71 4603.53,1654.23 4700.73,1654.23 4771.3,1724.8 4836.8,1724.8 4878.29,1766.29 5106.71,1766.29 5131.96,1741.04 5263.75,1741.04 5347.21,1824.5 5547.74,1824.5 5576.49,1853.25 v1(5793.08,1853.25) ; v1(5574.59,812.43) 5600.18,786.84 U49.6@5652.8,786.84
  Bottom Layer w5.3: v1(5574.59,812.43) 5574.59,869.86 5663.53,958.8 5875.3,958.8 5933.8,1017.3 5933.8,1638 5860.24,1711.56 5860.24,1786.09 v1(5793.08,1853.25)
PR0_PRU0_GPIO9: U1.F17 U49.9 | length 4096.7
  Top Layer w4: U1.F17@4051.07,1225.32 4066.82,1241.06 4113.02,1241.06 4114.06,1240.02
  Top Layer w5.3: 4114.06,1240.02 4119.55,1234.53 4178.39,1234.53 4218.26,1274.39 4257.46,1274.39 4273.91,1290.84 4399.4,1290.84 4414.17,1276.07 4443.95,1246.28 4464.89,1246.28 4479.52,1260.92 4479.52,1408.03 4433.88,1453.68 4433.88,1704.37 4475.51,1746 4818.93,1746 4860.42,1787.49 5115.49,1787.49 5140.74,1762.24 5254.97,1762.24 5338.43,1845.7 5538.96,1845.7 5608.26,1915 v1(5995,1915) ; v1(5835,735.66) U49.9@5877.2,735.66
  Bottom Layer w5.3: v1(5835,735.66) 5931.61,735.66 6158.11,962.16 6158.11,1693.74 6141.82,1710.03 6141.82,1766.44 5995,1913.26 v1(5995,1915)
PR0_PRU0_GPIO9_MUX: U49.10 U52.40 | length 1888.2
  Top Layer w5.3: v1(4538.82,440) 4555.16,456.34 U52.40@4555.16,496.77 ; U49.10@5877.2,761.25 5920,761.25 5948,733.25 5948,597.48 v1(5955.48,590)
  SIG 1 w4.75: v1(4538.82,440) 4558.07,420.75 4670.89,420.75 4684.09,433.95 5077.86,433.95 5179.61,535.7 5179.61,628.47 5192.17,641.03 5192.31,640.9 5569.84,640.9 5626.25,584.48 5755.01,584.48 5760.53,590 v1(5955.48,590)
PR0_PRU0_GPIO10: R286.1 U49.12 | length 3427.8
  Top Layer w5.3: R286.1@4342.07,1238.88 4357.1,1223.85 4472.43,1223.85 4500.72,1252.14 4500.72,1455.1 4588.41,1542.79 4588.41,1618.54 4612.29,1642.41 4714.55,1642.41 4784.96,1712.82 4840.58,1712.82 4883.45,1755.69 5102.32,1755.69 5127.57,1730.44 5268.14,1730.44 5351.6,1813.9 5552.13,1813.9 5571.96,1833.72 5924.62,1833.72 v1(5944.14,1853.25) ; U49.12@5877.2,812.43 5911.5,812.43 v1(5927.62,796.31)
  Bottom Layer w5.3: v1(5927.62,796.31) 5977.28,796.31 6147.51,966.55 6147.51,1689.35 6131.22,1705.64 6131.22,1762.05 6040.02,1853.25 v1(5944.14,1853.25)
PR0_PRU0_GPIO10_MUX: J1/J3.8 U49.13 | length 4440.4
  Top Layer w5.3: v1(5108.61,414.82) 5108.72,414.7 5385,414.7 5435,464.7 5435,638.6 5475,678.6 5564.85,678.6 5609.88,633.56 5694.94,633.56 5800,738.62 5800,812.74 5825.28,838.02 U49.13@5877.2,838.02
  Bottom Layer w5.3: J1/J3.8@2304.17,250 2349.17,205 2524.5,205 2550.5,231 2550.5,335.31 2563.3,348.11 2630.08,348.11 2684.59,402.62 2891.35,402.62 2915.09,378.88 3185.17,378.88 3200.92,363.13 3201.04,363.13 3256.78,307.38 3460.04,307.38 3487.31,280.11 3583.15,280.11 3600.21,263.05 3634.8,263.05 3659.53,287.78 3704.36,287.78 3736.92,255.22 3902.65,255.22 3967.2,190.67 3983.38,190.67 4043.72,130.34 4128.72,130.34 4138.51,120.55 4776.87,120.55 4834.12,177.8 5022.79,177.8 5108.61,263.63 v1(5108.61,414.82)
PR0_PRU0_GPIO10_R: R286.2 U1.G18 | length 234.2
  Top Layer w4: U1.G18@4082.57,1193.82 4114.06,1193.82
  Top Layer w5.3: 4114.06,1193.82 4196.07,1193.82 4215.59,1213.33 4259.42,1213.33 4282.27,1236.18 4289.05,1236.18 R286.2@4296.24,1243.37
PR0_PRU0_GPIO11: R75.1 U23.11 | length 638.6
  Top Layer w5.3: v1(4709.76,1417.13) U23.11@4762.24,1417.13
  Bottom Layer w5.3: R75.1@4473.25,1029.85 4504.23,1060.84 4504.23,1207.24 4615.86,1318.86 4728.68,1318.86 4740.77,1330.96 4740.77,1401.6 4725.24,1417.13 v1(4709.76,1417.13)
PR0_PRU0_GPIO11_MUX: U23.28 U52.42 | length 1564.7
  Top Layer w5.3: U52.42@4594.53,496.77 4594.53,459.12 4604.81,448.84 v1(4624.81,448.84) ; U23.28@4892.17,1417.13 4964.13,1417.13 v1(4983.82,1397.44)
  Bottom Layer w5.3: v1(4624.81,448.84) 4635.26,438.39 4873.39,438.39 4883.84,448.84 5041.02,606.02 5041.02,700.32 5111.64,770.95 5111.64,1008.44 5117.27,1014.07 5117.27,1305.63 5026.09,1396.81 4984.45,1396.81 v1(4983.82,1397.44)
PR0_PRU0_GPIO11_R: R75.2 U1.M16 | length 429.4
  Top Layer w10: U1.M16@4019.57,1036.34 v1(4035.32,1020.59)
  SIG 1 w4: v1(4035.32,1020.59) 4076.55,1020.59
  SIG 1 w4.75: 4076.55,1020.59 4096.35,1020.59 4113.74,1037.99 4114.06,1037.99 4217.23,1037.99 4223.64,1031.58 v1(4403.87,1031.58)
  Bottom Layer w5.3: v1(4403.87,1031.58) 4430.22,1031.58 R75.2@4431.93,1029.87
PR0_PRU0_GPIO12: R76.1 U23.12 | length 538.7
  Top Layer w5.3: R76.1@4471.93,1029.87 v1(4471.93,1056.95) ; v1(4659.76,1377.76) 4679.45,1397.44 U23.12@4762.24,1397.44
  Bottom Layer w5.3: v1(4471.93,1056.95) 4475.96,1056.95 4493.63,1074.62 4493.63,1211.63 v1(4659.76,1377.76)
PR0_PRU0_GPIO12_MUX: J1/J3.5 U23.26 | length 6883.1
  Top Layer w5.3: U23.26@4892.17,1377.76 5051.06,1377.76 5089.52,1416.23 5089.52,1690.48 v1(5050,1730)
  SIG 1 w4.75: v1(1489.72,2069.3) 1530.54,2069.3 1589.63,2128.39 1746.63,2128.39 1875.87,2257.63 2903.73,2257.63 3048.77,2112.59 3048.77,2092.7 3078.24,2061.38 ccw(c3173.18,2150) 3083.76,2055.81 3121.35,2020.12 3227.82,2020.12 3449.11,2241.42 4264.81,2241.42 4384,2122.23 4467.34,2122.23 4474.09,2115.47 4738.53,2115.47 4756.5,2097.5 4756.5,1920.5 4947,1730 v1(5050,1730)
  Bottom Layer w5.3: v1(1489.72,2069.3) 1520.7,2069.3 1541,2049 1541,1926.77 1584.27,1883.5 1698.53,1883.5 1711.6,1870.43 1711.6,1758.01 1703.86,1750.27 1703.86,1637.19 1685.55,1618.88 1685.55,1522.14 1741.2,1466.49 1741.2,1411.65 1922.76,1230.09 1922.76,1178.81 1951.78,1149.78 1951.78,1080.22 1946.68,1075.11 1946.68,974.63 1985.02,936.28 1985.02,769.27 1990.96,763.34 1990.96,495.47 2014.4,472.02 2014.4,416.57 2053.45,377.52 2053.45,299.28 J1/J3.5@2004.17,250
PR0_PRU0_GPIO12_R: R76.2 U1.M15 | length 507.1
  Top Layer w5.3: R76.2@4432.56,1029.87 v1(4432.56,1056.95)
  Top Layer w10: U1.M15@3988.08,1036.34 v1(4003.83,1020.59)
  SIG 1 w4.75: v1(4003.83,1020.59) 4019.95,1036.71 4097.56,1036.71 4110.79,1049.95 4114.06,1049.95 4199.53,1049.95 4223.37,1073.79 4384.39,1073.79 4401.22,1056.95 v1(4432.56,1056.95)
PR0_PRU0_GPIO13: R77.1 U23.13 | length 796.4
  Top Layer w5.3: R77.1@4339.94,1204.08 4375.01,1204.08 v1(4376.57,1202.52) ; v1(4720.59,1377.76) U23.13@4762.24,1377.76
  Bottom Layer w5.3: v1(4376.57,1202.52) 4376.57,1174.58 4359.79,1157.8 4335.33,1157.8 4322.41,1170.72 4322.41,1200.61 4353.88,1232.08 4420,1232.08 4426.47,1238.55 4426.47,1270.28 4467.17,1310.97 4467.17,1370.24 4473.67,1376.74 4497.43,1376.74 4504.17,1370 4504.17,1354.93 4511.92,1347.18 4586.06,1347.18 4658.88,1420 4678.35,1420 v1(4720.59,1377.76)
PR0_PRU0_GPIO13_MUX: U23.24 U51.10 | length 949
  Top Layer w5.3: v1(4464,1589.53) 4489.59,1563.94 U51.10@4542.2,1563.94 ; U23.24@4892.17,1338.39 5026.38,1338.39 v1(5026.97,1338.98)
  SIG 1 w4.75: v1(4464,1589.53) 4484.37,1569.15 4510.85,1569.15 4642.75,1437.25 4736.95,1437.25 4769.71,1404.49 4769.71,1360.78 4789.65,1340.83 4851.94,1340.83 4893.32,1299.45 4941.79,1299.45 4981.16,1338.82 5026.82,1338.82 v1(5026.97,1338.98)
PR0_PRU0_GPIO13_R: R77.2 U1.H17 | length 259.5
  Top Layer w4: U1.H17@4051.07,1162.32 4067.21,1178.46 4114.06,1178.46
  Top Layer w5.3: 4114.06,1178.46 4206.06,1178.46 4230.33,1202.73 4263.81,1202.73 4268.54,1207.47 R77.2@4291.91,1207.47
PR0_PRU0_GPIO14: R78.1 U23.14 | length 204
  Top Layer w5.3: R78.1@4576.85,1313.21 4620,1313.21 4664.86,1358.07 U23.14@4762.24,1358.07
PR0_PRU0_GPIO14_MUX: U23.22 U51.6 | length 1124.1
  Top Layer w5.3: v1(4239.59,1615.12) 4265.18,1589.53 U51.6@4317.8,1589.53 ; U23.22@4892.17,1299.02 4954.13,1299.02 v1(4983.82,1269.33)
  SIG 1 w4.75: v1(4239.59,1615.12) 4337.74,1516.97 4410.95,1516.97 4462.23,1465.69 4532.88,1465.69 4590.05,1408.51 4590.05,1349.95 4590.05,1347.98 4654.2,1281.2 ccw(c4668.09,1294.53) 4655.29,1280.14 4678.78,1259.25 4680.74,1259.25 4973.74,1259.25 v1(4983.82,1269.33)
PR0_PRU0_GPIO14_R: R78.2 U1.H16 | length 966.1
  Top Layer w5.3: v1(4401.72,1176.77) 4403.2,1175.29 4459.85,1175.29 4522.9,1238.33 4522.9,1298.64 4528.32,1304.05 4528.32,1306.02 4535.51,1313.21 R78.2@4537.48,1313.21
  Top Layer w10: U1.H16@4019.57,1162.32 v1(4035.32,1178.07)
  SIG 1 w4.75: v1(4035.32,1178.07) 4034.58,1178.07 4019.14,1162.63 3903.65,1162.63 3893.96,1152.94 3893.96,1132.7 3900.35,1126.31 4043.65,1126.31 4106.81,1189.47 4114.06,1189.47 4362.4,1189.47 4373.79,1178.08 4400.4,1178.08 v1(4401.72,1176.77)
PR0_PRU0_GPIO15: R79.1 U23.15 | length 606.3
  Top Layer w5.3: v1(4720.59,1338.39) U23.15@4762.24,1338.39
  Bottom Layer w5.3: R79.1@4469.35,1086.88 4469.35,1108.3 4464.16,1113.49 4436.87,1113.49 4433.77,1116.6 4433.77,1147.37 4436.87,1150.48 4456.91,1150.48 4461.67,1155.23 4461.67,1245.15 4547.65,1331.13 4585,1331.13 4651.15,1397.28 4672.05,1397.28 4719.08,1350.25 4719.08,1339.9 v1(4720.59,1338.39)
PR0_PRU0_GPIO15_MUX: J2/J4.12 U23.20 | length 4093
  Top Layer w5.3: U23.20@4837.05,1283.27 4837.05,1222.41 4849.89,1209.57 4952.79,1209.57 5017.02,1273.8 5017.02,1297.5 5100.12,1380.6 5100.12,1708.32 5094.06,1714.38 v1(5094.06,1735.02)
  SIG 1 w4.75: J2/J4.12@2404.17,2050 2404.17,2154.21 2436.31,2186.34 2649.69,2186.34 2675.16,2160.87 2970.77,2160.87 3028.12,2103.52 3028.12,2041.68 3048.48,2021.32 3088.98,2021.32 3110.83,1999.47 3236.37,1999.47 3457.66,2220.77 4255.98,2220.77 4375.94,2100.81 4425.22,2100.81 4454.98,2071.05 4454.98,1934.26 4480,1909.24 4626.07,1909.24 4776.68,1758.62 4886.03,1758.62 4943.54,1701.11 5060.14,1701.11 v1(5094.06,1735.02)
PR0_PRU0_GPIO15_R: R79.2 U1.L16 | length 461.3
  Top Layer w10: U1.L16@4019.57,1067.84 v1(4035.32,1052.09)
  SIG 1 w4.75: v1(4035.32,1052.09) 4043.24,1060 4114.06,1060 4174.15,1060 4233.89,1119.74 4371.08,1119.74 4402.65,1088.17 v1(4402.65,1086.43)
  Bottom Layer w5.3: v1(4402.65,1086.43) 4420.82,1086.43 4420.82,1087.9 R79.2@4429.98,1086.88
PR0_PRU0_GPIO16: R80.1 U23.16 | length 937.9
  Top Layer w5.3: R80.1@4335.8,1168.86 4376.75,1168.86 4388.37,1157.24 4409.81,1157.24 4409.88,1157.32 4458.65,1157.32 4494.62,1193.28 4523.26,1193.28 4535.6,1205.63 4535.6,1287.55 4538.7,1290.65 4560.03,1290.65 4563.14,1287.55 4563.14,1200.44 4569.39,1194.19 4582.16,1194.19 4589.07,1201.1 4589.07,1285.11 4596.81,1292.85 4611,1292.85 4619.2,1284.65 4619.2,1200.29 4625.94,1193.54 4639.04,1193.54 4645.5,1200 4645.5,1307.42 4677.27,1339.2 4689.83,1339.2 4710.32,1318.7 U23.16@4762.24,1318.7
PR0_PRU0_GPIO16_MUX: U23.18 U51.3 | length 953.3
  Top Layer w5.3: v1(4270,1652.62) 4283.68,1666.3 U51.3@4317.8,1666.3 ; v1(4797.68,1240.01) U23.18@4797.68,1283.27
  SIG 1 w4.75: v1(4270,1652.62) 4234.29,1652.62 4220,1638.33 4220,1602.91 4315.98,1506.92 4406.78,1506.92 4458.07,1455.64 4528.71,1455.64 4580,1404.35 4580,1340.81 4679.81,1241.01 4796.67,1241.01 v1(4797.68,1240.01)
PR0_PRU0_GPIO16_R: R80.2 U1.H18 | length 255.2
  Top Layer w5.3: U1.H18@4082.57,1162.32 4152.03,1162.32 4177.22,1137.13 4205.75,1137.13 4218.28,1149.66 4218.28,1162.95 4232.64,1177.32 4284.16,1177.32 4285.43,1176.05 4290.03,1176.05 R80.2@4298.75,1167.33
PRU/BP_MUX_EN_INV: R96.2 U46.4 U49.15 U51.15 | length 2815.8
  Top Layer w5.3: U51.15@4542.2,1691.89 4578.14,1691.89 4604.13,1665.9 4686.4,1665.9 4703.5,1683 v1(4703.5,1711.5) ; U49.15@5877.2,889.2 5924.04,889.2 v1(5931,882.24) 5946.5,866.74 5946.5,808.04 5958.17,796.38 R96.2@5986.5,796.38 6012.17,770.71 U46.4@6054.41,770.71
  Bottom Layer w5.3: v1(4703.5,1711.5) 4777.12,1785.12 5001.98,1785.12 5192.93,1976.07 5714.42,1976.07 5922.85,1767.64 5922.85,1735.14 5971.25,1686.74 5971.25,1381.75 5983.45,1369.55 5983.45,1019.45 5931,967 v1(5931,882.24)
RESETN_PB: Q2.2 R178.1 SW3.2 SW3.4 U33.2 | length 636.8
  Top Layer w5.3: SW3.2@839.76,2217.46 934,2217.46 939,2217.46 ; R178.1@891.62,1973 894.19,1975.56 898.84,1980.22 912.22,1980.22 937,2005 969.35,2005 Q2.2@973.76,2000.6 ; R178.1@891.62,1975.56 891.62,2007.38 875,2024 875,2053 880,2058 U33.2@906,2058 ; U33.2@906.29,2059 933,2059 939,2065 939,2212 ; 934,2217 939,2212 ; 943.72,2217.46 939,2217.46 ; 943.74,2217.42 SW3.4@1060.19,2217.42 ; 944,2217 939,2212 ; 939,2212 939,2217.46
RGMII1_ICSSM_MUX_EN: R292.2 R294.2 U50.8 | length 4868
  Top Layer w5.3: v1(3052.37,756.89) 3052.96,756.3 3052.96,695.53 3122.73,625.75 3122.73,487.03 3112.25,476.55 3112.25,337.83 3146.85,303.23 3261.21,303.23 3282.52,281.92 3282.52,224.72 3304.54,202.69 3304.54,91 3352.89,42.65 4178.07,42.65 4215.42,80 4601.77,80 4639.12,42.65 5726.23,42.65 5750,66.42 v1(5750,66.69) ; U50.8@5303.35,1000.35 5397.83,1000.35 5454.5,1057.02 R292.2@5477.76,1057.02 R294.2@5477.76,992.02 5477.76,976.31 5489.74,964.33 5722.88,964.33 5760,927.2 v1(5760,815.75)
  Bottom Layer w5.3: v1(5750,66.69) 5750,162.32 5835.4,247.72 5835.4,322.19 5844.03,330.82 5844.03,435.12 5760,519.15 v1(5760,815.75)
RGMII1_ICSSM_MUX_SEL_GPIO105: R291.2 R293.2 U1.D17 U17.1 U17.5 U50.9 U50.10 | length 3847.9
  Top Layer w5.3: U1.D17@4051.07,1288.31 4068.04,1305.28 4090.41,1305.28 4130.23,1345.1 4152.34,1345.1 4197.79,1390.55 4350.21,1390.55 4358.46,1382.3 4383.42,1382.3 4411.7,1410.57 4411.7,1712.17 4467.3,1767.78 4803.07,1767.78 4843.98,1808.69 5124.27,1808.69 5140.6,1792.36 v1(5242.49,1792.36) ; v1(4752.96,1057.75) 4776.02,1080.8 4917.18,1080.8 5034.52,1198.14 5034.52,1259.78 5099.74,1325 v1(5345,1325) 5397.09,1325 5452.19,1269.9 5452.19,1158.84 5464.21,1146.82 5464.21,1130.65 5463.99,1130.43 5463.99,1110.8 5464.21,1110.59 5464.21,1090.92 5458.38,1085.09 ; U50.9@5303.35,1020.04 5366.48,1020.04 5374.87,1028.43 ; U50.10@5303.35,1039.72 5363.57,1039.72 5374.87,1028.43 ; 5458.75,1084.72 5402.46,1028.43 5374.87,1028.43
  Bottom Layer w5.3: R293.2@4591.64,1215.33 4588.62,1212.32 R291.2@4588.62,1152.36 4610,1152.36 4618.69,1143.67 4618.69,1097.35 4632.92,1083.12 U17.5@4680.08,1083.12 4740.77,1083.12 4752.86,1071.02 4752.86,1057.85 v1(4752.96,1057.75) 4752.84,1057.62 4752.84,1017.37 4739.85,1004.38 U17.1@4680.08,1004.38 ; v1(5242.49,1792.36) 5242.49,1428.84 5307.28,1364.05 5318.72,1352.61 5345,1326.33 v1(5345,1325)
RJ45_1_LED1_GREEN: J7.11 R224.2 | length 600.5
  SIG 1 w5.3: v1(7211.61,1143.99) 7228.7,1161.08 7468.28,1161.08 7539.08,1090.28 J7.11@7539.08,919.76
  Bottom Layer w5.3: R224.2@7160.2,1111.38 7181.03,1111.38 7211.61,1141.96 v1(7211.61,1143.99)
RJ45_1_LED1_YELLOW: J7.12 Q4.3 | length 737.4
  SIG 1 w5.3: v1(7203.26,1097.87) 7203.26,1121.11 7192.09,1132.28 7192.09,1152.08 7216.65,1176.63 7467.72,1176.63 7587.58,1056.77 7587.58,1031.72 7619,1000.29 J7.12@7619,919.76
  Bottom Layer w5.3: v1(7203.26,1097.87) 7203.65,1098.26 7268.59,1098.26 Q4.3@7274.1,1092.76
RJ45_1_LED2_GREEN: J7.13 Q5.3 R226.1 | length 377.3
  Top Layer w5.3: Q5.3@7324,160.9 R226.1@7324,221.46 7424.43,221.46 7539.08,336.1 J7.13@7539.08,390.24
RJ45_1_LED2_YELLOW: J7.14 Q6.3 R228.1 | length 425.5
  Bottom Layer w5.3: Q6.3@7324,160.9 R228.1@7324,221.46 7424.43,221.46 7512.97,310 7538.76,310 J7.14@7619,390.24
RJ45_1_VCC: J7.2 J8.2 TP21.1 TP22.1 | length 1601.1
  Top Layer w10: v1(6975,1174.56) TP21.1@6975,1345.45 7150.65,1345.45 7189.08,1383.88 J8.2@7189.08,1470 ; TP22.1@7165,225 7189.08,249.08 J7.2@7189.08,480
  SIG 1 w10: v1(6975,1174.56) 7021.66,1127.91 7021.66,535 7076.66,480 J7.2@7189.08,480
RJ45_2_LED1_GREEN: J8.11 R230.2 | length 415
  Bottom Layer w5.3: R230.2@7220,2141.38 7247.83,2141.38 7399.21,1990 7458.84,1990 J8.11@7539.08,1909.76
RJ45_2_LED1_YELLOW: J8.12 Q7.3 | length 407.6
  Bottom Layer w5.3: Q7.3@7340,2117.76 7340,2088.61 7428.01,2000.6 7571.54,2000.6 7619,1953.14 J8.12@7619,1909.76
RJ45_2_LED2_GREEN: J8.13 Q8.3 R232.1 | length 263.5
  Bottom Layer w5.3: Q8.3@7433.87,1187.91 R232.1@7433.87,1251.28 7443.03,1260.44 7452.21,1260.44 7455.31,1263.54 7455.31,1267.25 7461.2,1273.14 7499.14,1273.14 7539.08,1313.08 J8.13@7539.08,1380.24
RJ45_2_LED2_YELLOW: J8.14 Q9.3 R234.1 | length 209.6
  Bottom Layer w5.3: Q9.3@7580.33,1186.64 R234.1@7580.33,1250 7580.33,1341.56 J8.14@7619,1380.24
SD_PWR_EN: R39.2 U8.3 U9.4 | length 2017.8
  Top Layer w5.3: U8.3@795.16,716 829.3,716 847.55,734.25 v1(847.55,789.62)
  SIG 1 w4.75: v1(847.55,789.62) 940.38,789.62 985,745 985,698 1015.48,667.52 1026.76,656.24 1042.7,656.24 1081.59,695.13 1116.73,695.13 1142.19,669.68 1378.96,669.68 1469.98,760.7 1469.98,1054.85 1556.1,1140.97 1657.08,1140.97 1801.54,1285.44 1894.86,1285.44 1938.67,1329.24 1976.1,1329.24 1994.22,1347.36 1994.22,1376.74 1973.75,1397.21 v1(1973.75,1482.88)
  Bottom Layer w5.3: U9.4@1942.75,1514.8 1950.62,1514.8 1971.32,1494.1 1971.32,1485.31 v1(1973.75,1482.88)
SHIELD1: C229.2 J5.1 J5.2 J5.3 J5.4 R32.1
SHIELD2: C235.2 J7.15 J7.16 R254.1
SHIELD3: C247.2 J8.15 J8.16 R255.1
SHIELD4: C230.2 J34.6 J34.7 J34.8 J34.9 J34.10 J34.11 R253.1
SOC_TA_I2C3_SCL: R355.1 R412.2 | length 672.3
  Top Layer w5.3: R412.2@745.39,1864.66 772.95,1864.66 839.67,1931.38 960.78,1931.38 988.32,1958.92 1035.12,1958.92 1058.97,1935.07 1144.2,1935.07 1199.61,1879.65 1278.42,1879.65 1302.64,1903.88 v1(1305.16,1903.88)
  Bottom Layer w5.3: R355.1@1288.1,1927.43 1288.1,1923.49 1305.16,1906.44 v1(1305.16,1903.88)
SOC_TA_I2C3_SDA: R357.1 R410.2 | length 783.8
  Top Layer w5.3: R410.2@875.14,1864.66 897.86,1887.38 897.86,1900.02 918.62,1920.78 965.17,1920.78 992.71,1948.32 1030.73,1948.32 1054.58,1924.47 1139.81,1924.47 1195.22,1869.05 1282.81,1869.05 1298.11,1884.36 1313.25,1884.36 1336.26,1907.36 1336.26,1957.2 1354.12,1975.06 1444.06,1975.06 v1(1461,1992)
  Bottom Layer w5.3: v1(1461,1992) 1461.48,1992.48 1486.84,1992.48 1496,1983.32 R357.1@1496,1979.38
SOP0_SW: R14.2 SW1.8 U3.2 U4.6 | length 599.3
  Top Layer w5.3: U3.2@3338.21,363.58 3338.21,327.25 3317.18,306.22 3317.18,296.66 3316.88,296.36 3316.88,244.04 3336.34,224.58 3336.34,158.06 3350.83,143.58 3430.94,143.58 3435.55,138.97 3435.55,119.51 v1(3470.3,119.51) SW1.8@3512.3,119.51
  Bottom Layer w5.3: v1(3470.3,119.51) 3494.01,119.51 3554.41,179.91 U4.6@3618.83,179.91
SOP1_SW: R15.2 SW1.7 U3.3 U4.7 | length 525.3
  Top Layer w5.3: U3.3@3357.9,363.58 3357.9,324.9 3327.78,294.78 3327.78,292.27 3327.48,291.97 3327.48,248.43 3346.94,228.97 3346.94,213.09 3366.87,193.16 3431.35,193.16 3435.55,188.97 3435.55,169.51 v1(3470.3,169.51) SW1.7@3512.3,169.51
  Bottom Layer w5.3: v1(3470.3,169.51) 3516.01,169.51 3542.15,195.65 U4.7@3618.83,195.65
SOP2_SW: R16.2 SW1.6 U3.4 U4.8 | length 476.2
  Top Layer w5.3: U3.4@3377.58,363.58 3377.58,327.08 3338.08,287.58 3338.08,252.82 3349.82,241.09 3353.63,241.09 3353.88,240.83 3370.06,240.83 3370.88,241.65 3427.87,241.65 3435.55,233.97 3435.55,219.51 v1(3470.3,219.51) SW1.6@3512.3,219.51
  Bottom Layer w5.3: v1(3470.3,219.51) 3581.42,219.51 3589.52,211.4 U4.8@3618.83,211.4
SOP3_SW: R17.2 SW1.5 U3.5 U4.9 | length 423.7
  Top Layer w5.3: U3.5@3403.17,389.17 3422,389.17 3435.55,375.62 3435.55,269.51 v1(3470.3,269.51) SW1.5@3512.3,269.51
  Bottom Layer w5.3: v1(3470.3,269.51) 3578.76,269.51 3595.82,252.45 3626.12,252.45 3642.45,236.12 U4.9@3642.45,219.28
SOP_DRIVE_OEN_R: R18.1 U5.4 | length 88.4
  Top Layer w5.3: U5.4@2028.71,965.53 2028.71,973.41 2047.77,992.46 2047.77,1010.18 2035.53,1022.42 2035.53,1034.66 R18.1@2031.05,1039.14
SOP_DRIVER_OEN: R18.2 R20.1 U4.1 U4.16 | length 3472.9
  Top Layer w5.3: v1(1932.26,1100.31) 1948.94,1116.99 2071.32,1116.99 2074.43,1113.89 R20.1@2074.43,1094.07 R18.2@2074.43,1039.07
  SIG 1 w4.75: v1(1846,173) 2203.69,173 2311.69,65 2649.34,65 2693.8,109.46 2895.59,109.46 3099.96,313.83 3266.41,313.83 3338.87,241.36 3353.74,241.36 3354,241.1 3369.94,241.1 3370.2,241.36 3516.53,241.36 3605.89,152 3656.28,152 3665.04,143.24 v1(3710.76,143.24)
  Bottom Layer w5.3: v1(1846,173) 1784,173 1754.13,202.87 1754.13,379.85 1903.09,528.8 1945.98,571.69 1945.98,885.08 1970.28,909.38 1970.28,936.04 1936.08,970.24 1936.08,1066.62 1932.26,1070.44 v1(1932.26,1100.31) ; U4.1@3689.69,158.25 3689.69,148.41 3690.98,147.12 3703.43,147.12 3707.32,143.24 v1(3710.76,143.24) ; v1@3710.76,142.41 3713.32,142.41 U4.16@3713.32,164.16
